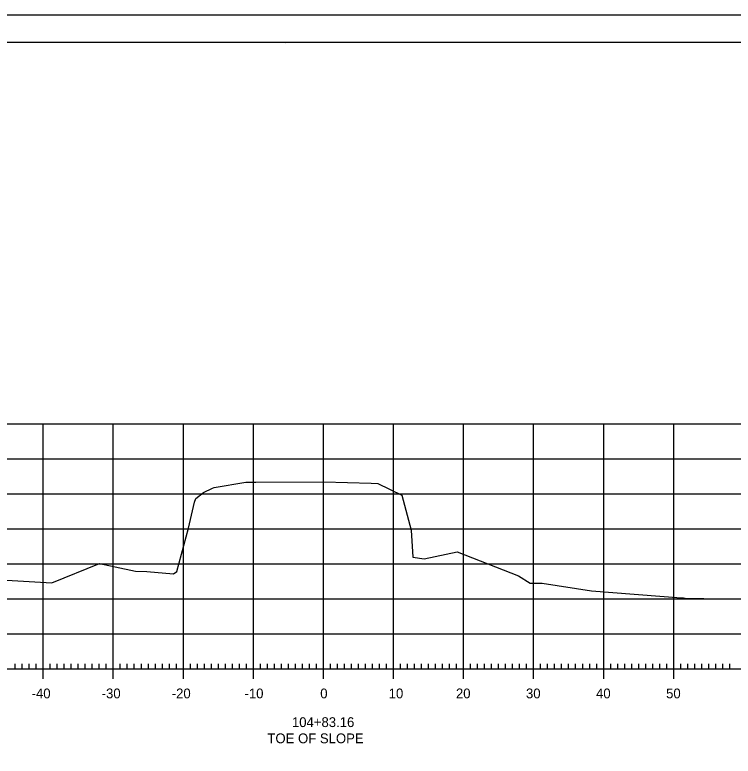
# Model space of a CAD drawing. Extents: x 961436 to 1372525, y 380079 to 2027791.
# Drawn here: x 1371150.8 to 1371253.4, y 380429.9 to 380535.8 of the extents above; entities that cross this region are included whole.
import ezdxf

# ---------------------------------------------------------------- set-up
doc = ezdxf.new("R2010")
doc.units = 0
for name, color, linetype in [('R_Axis', 7, 'Continuous'), ('R_Axis Annot', 7, 'Continuous'), ('R_Border', 7, 'Continuous'), ('R_Exist Surface', 7, 'Continuous'), ('R_Grid', 7, 'Continuous'), ('R_No Plot', 7, 'Continuous')]:
    doc.layers.add(name, color=color, linetype=linetype)

msp = doc.modelspace()

# ---------------------------------------------------------------- linework, layer by layer
at = {"layer": 'R_Axis'}
for p, q in [((1371150.88, 380442.4), (1371150.88, 380443.1)), ((1371151.88, 380442.4), (1371151.88, 380443.1)), ((1371152.88, 380442.4), (1371152.88, 380443.1)), ((1371153.88, 380442.4), (1371153.88, 380443.1)), ((1371154.88, 380441), (1371154.88, 380443.8)), ((1371155.88, 380442.4), (1371155.88, 380443.1)), ((1371156.88, 380442.4), (1371156.88, 380443.1)), ((1371157.88, 380442.4), (1371157.88, 380443.1)), ((1371158.88, 380442.4), (1371158.88, 380443.1)), ((1371159.88, 380442.4), (1371159.88, 380443.1)), ((1371160.88, 380442.4), (1371160.88, 380443.1)), ((1371161.88, 380442.4), (1371161.88, 380443.1)), ((1371162.88, 380442.4), (1371162.88, 380443.1)), ((1371163.88, 380442.4), (1371163.88, 380443.1)), ((1371164.88, 380441), (1371164.88, 380443.8)), ((1371165.88, 380442.4), (1371165.88, 380443.1)), ((1371166.88, 380442.4), (1371166.88, 380443.1)), ((1371167.88, 380442.4), (1371167.88, 380443.1)), ((1371168.88, 380442.4), (1371168.88, 380443.1)), ((1371169.88, 380442.4), (1371169.88, 380443.1)), ((1371170.88, 380442.4), (1371170.88, 380443.1)), ((1371171.88, 380442.4), (1371171.88, 380443.1)), ((1371172.88, 380442.4), (1371172.88, 380443.1)), ((1371173.88, 380442.4), (1371173.88, 380443.1)), ((1371174.88, 380441), (1371174.88, 380443.8)), ((1371175.88, 380442.4), (1371175.88, 380443.1)), ((1371176.88, 380442.4), (1371176.88, 380443.1)), ((1371177.88, 380442.4), (1371177.88, 380443.1)), ((1371178.88, 380442.4), (1371178.88, 380443.1)), ((1371179.88, 380442.4), (1371179.88, 380443.1)), ((1371180.88, 380442.4), (1371180.88, 380443.1)), ((1371181.88, 380442.4), (1371181.88, 380443.1)), ((1371182.88, 380442.4), (1371182.88, 380443.1)), ((1371183.88, 380442.4), (1371183.88, 380443.1)), ((1371184.88, 380441), (1371184.88, 380443.8)), ((1371185.88, 380442.4), (1371185.88, 380443.1)), ((1371186.88, 380442.4), (1371186.88, 380443.1)), ((1371187.88, 380442.4), (1371187.88, 380443.1)), ((1371188.88, 380442.4), (1371188.88, 380443.1)), ((1371189.88, 380442.4), (1371189.88, 380443.1)), ((1371190.88, 380442.4), (1371190.88, 380443.1)), ((1371191.88, 380442.4), (1371191.88, 380443.1)), ((1371192.88, 380442.4), (1371192.88, 380443.1)), ((1371193.88, 380442.4), (1371193.88, 380443.1)), ((1371194.88, 380441), (1371194.88, 380443.8)), ((1371195.88, 380442.4), (1371195.88, 380443.1)), ((1371196.88, 380442.4), (1371196.88, 380443.1)), ((1371197.88, 380442.4), (1371197.88, 380443.1)), ((1371198.88, 380442.4), (1371198.88, 380443.1)), ((1371199.88, 380442.4), (1371199.88, 380443.1)), ((1371200.88, 380442.4), (1371200.88, 380443.1)), ((1371201.88, 380442.4), (1371201.88, 380443.1)), ((1371202.88, 380442.4), (1371202.88, 380443.1)), ((1371203.88, 380442.4), (1371203.88, 380443.1)), ((1371204.88, 380441), (1371204.88, 380443.8)), ((1371205.88, 380442.4), (1371205.88, 380443.1)), ((1371206.88, 380442.4), (1371206.88, 380443.1)), ((1371207.88, 380442.4), (1371207.88, 380443.1)), ((1371208.88, 380442.4), (1371208.88, 380443.1)), ((1371209.88, 380442.4), (1371209.88, 380443.1)), ((1371210.88, 380442.4), (1371210.88, 380443.1)), ((1371211.88, 380442.4), (1371211.88, 380443.1)), ((1371212.88, 380442.4), (1371212.88, 380443.1)), ((1371213.88, 380442.4), (1371213.88, 380443.1)), ((1371214.88, 380441), (1371214.88, 380443.8)), ((1371215.88, 380442.4), (1371215.88, 380443.1)), ((1371216.88, 380442.4), (1371216.88, 380443.1)), ((1371217.88, 380442.4), (1371217.88, 380443.1)), ((1371218.88, 380442.4), (1371218.88, 380443.1)), ((1371219.88, 380442.4), (1371219.88, 380443.1)), ((1371220.88, 380442.4), (1371220.88, 380443.1)), ((1371221.88, 380442.4), (1371221.88, 380443.1)), ((1371222.88, 380442.4), (1371222.88, 380443.1)), ((1371223.88, 380442.4), (1371223.88, 380443.1)), ((1371224.88, 380441), (1371224.88, 380443.8)), ((1371225.88, 380442.4), (1371225.88, 380443.1)), ((1371226.88, 380442.4), (1371226.88, 380443.1)), ((1371227.88, 380442.4), (1371227.88, 380443.1)), ((1371228.88, 380442.4), (1371228.88, 380443.1)), ((1371229.88, 380442.4), (1371229.88, 380443.1)), ((1371230.88, 380442.4), (1371230.88, 380443.1)), ((1371231.88, 380442.4), (1371231.88, 380443.1)), ((1371232.88, 380442.4), (1371232.88, 380443.1)), ((1371233.88, 380442.4), (1371233.88, 380443.1)), ((1371234.88, 380441), (1371234.88, 380443.8)), ((1371235.88, 380442.4), (1371235.88, 380443.1)), ((1371236.88, 380442.4), (1371236.88, 380443.1)), ((1371237.88, 380442.4), (1371237.88, 380443.1)), ((1371238.88, 380442.4), (1371238.88, 380443.1)), ((1371239.88, 380442.4), (1371239.88, 380443.1)), ((1371240.88, 380442.4), (1371240.88, 380443.1)), ((1371241.88, 380442.4), (1371241.88, 380443.1)), ((1371242.88, 380442.4), (1371242.88, 380443.1)), ((1371243.88, 380442.4), (1371243.88, 380443.1)), ((1371244.88, 380441), (1371244.88, 380443.8)), ((1371245.88, 380442.4), (1371245.88, 380443.1)), ((1371246.88, 380442.4), (1371246.88, 380443.1)), ((1371247.88, 380442.4), (1371247.88, 380443.1)), ((1371248.88, 380442.4), (1371248.88, 380443.1)), ((1371249.88, 380442.4), (1371249.88, 380443.1)), ((1371250.88, 380442.4), (1371250.88, 380443.1)), ((1371251.88, 380442.4), (1371251.88, 380443.1)), ((1371252.88, 380442.4), (1371252.88, 380443.1)), ((1371054.88, 380442.4), (1371334.88, 380442.4))]:
    msp.add_line(p, q, dxfattribs=at)
at = {"layer": 'R_Border'}
for p, q in [((1371036.88, 380531.86), (1371353.06, 380531.86)), ((1371189.4, 380531.6), (1371189.4, 380531.6)), ((1371189.4, 380531.6), (1371189.4, 380531.6))]:
    msp.add_line(p, q, dxfattribs=at)
at = {"layer": 'R_Exist Surface'}
msp.add_lwpolyline([(1371144.73, 380455.33), (1371156.11, 380454.69), (1371162.89, 380457.43), (1371168.05, 380456.34), (1371169.65, 380456.32), (1371173.45, 380455.96), (1371173.93, 380456.29), (1371175.63, 380462.51), (1371176.48, 380466.18), (1371176.65, 380466.74), (1371177.76, 380467.57), (1371179.02, 380468.21), (1371179.29, 380468.27), (1371183.79, 380469.05), (1371185.22, 380469.05), (1371194.94, 380469.09), (1371201.7, 380468.93), (1371202.64, 380468.87), (1371206.05, 380467.22), (1371206.06, 380467.2), (1371207.4, 380462.22), (1371207.66, 380458.33), (1371209.24, 380458.09), (1371213.97, 380459.11), (1371222.71, 380455.67), (1371224.38, 380454.62), (1371226.11, 380454.66), (1371233.13, 380453.56), (1371245.93, 380452.56), (1371246.26, 380452.54), (1371246.5, 380452.51), (1371251.89, 380452.42), (1371257.16, 380452.35)], dxfattribs=at)
at = {"layer": 'R_Grid'}
for p, q in [((1371054.88, 380477.4), (1371334.88, 380477.4)), ((1371154.88, 380442.4), (1371154.88, 380477.4)), ((1371164.88, 380442.4), (1371164.88, 380477.4)), ((1371174.88, 380442.4), (1371174.88, 380477.4)), ((1371184.88, 380442.4), (1371184.88, 380477.4)), ((1371194.88, 380442.4), (1371194.88, 380477.4)), ((1371204.88, 380442.4), (1371204.88, 380477.4)), ((1371214.88, 380442.4), (1371214.88, 380477.4)), ((1371224.88, 380442.4), (1371224.88, 380477.4)), ((1371234.88, 380442.4), (1371234.88, 380477.4)), ((1371244.88, 380442.4), (1371244.88, 380477.4)), ((1371054.88, 380472.4), (1371334.88, 380472.4)), ((1371054.88, 380467.4), (1371334.88, 380467.4)), ((1371054.88, 380462.4), (1371334.88, 380462.4)), ((1371054.88, 380457.4), (1371334.88, 380457.4)), ((1371054.88, 380452.4), (1371334.88, 380452.4)), ((1371054.88, 380447.4), (1371334.88, 380447.4)), ((1371054.88, 380442.4), (1371334.88, 380442.4))]:
    msp.add_line(p, q, dxfattribs=at)
at = {"layer": 'R_No Plot'}
msp.add_line((1371024.48, 380535.75), (1371357.81, 380535.75), dxfattribs=at)
for points in [[(1371024.47, 380535.75), (1371357.81, 380535.75), (1371357.81, 380322.41), (1371024.47, 380322.41)], [(1371270.8, 380531.86), (1371290.42, 380531.86), (1371290.42, 380521.98), (1371306.53, 380521.98), (1371329.73, 380521.98), (1371329.85, 380493.82), (1371353.06, 380493.82), (1371353.06, 380326.4), (1371036.88, 380326.4), (1371036.88, 380531.86)]]:
    msp.add_lwpolyline(points, close=True, dxfattribs=at)

# ---------------------------------------------------------------- texts
at = {"layer": 'R_Axis Annot'}
for s, p in [('-40', (1371153.22, 380438.2)), ('-30', (1371163.22, 380438.2)), ('-20', (1371173.22, 380438.2)), ('-10', (1371183.61, 380438.2)), ('0', (1371194.42, 380438.2)), ('10', (1371204.19, 380438.2)), ('20', (1371213.79, 380438.2)), ('30', (1371223.79, 380438.2)), ('40', (1371233.79, 380438.2)), ('50', (1371243.79, 380438.2)), ('104+83.16', (1371190.38, 380434.1)), ('TOE OF SLOPE', (1371186.88, 380431.79))]:
    msp.add_text(s, height=1.4, dxfattribs=at).set_placement(p)

doc.saveas('drawing.dxf')
